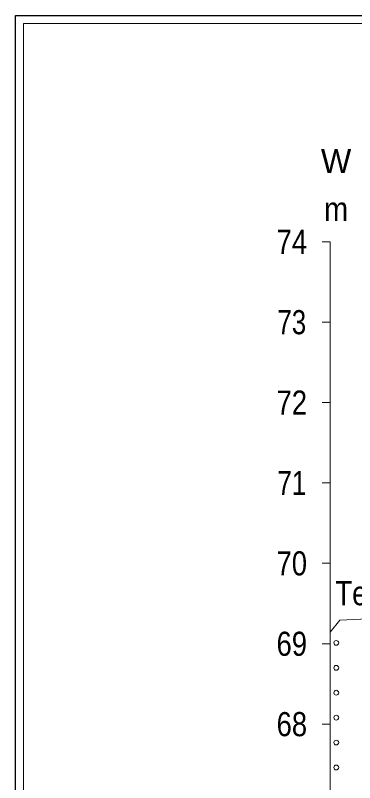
# Model space of a CAD drawing. Extents: x 640121 to 640955, y 6441885 to 6442246.
# Drawn here: x 640121.3 to 640163.5, y 6442150.7 to 6442246.2 of the extents above; entities that cross this region are included whole.
import ezdxf
from ezdxf.enums import TextEntityAlignment as Align

# ---------------------------------------------------------------- set-up
doc = ezdxf.new("R2010")
doc.units = 0
doc.header["$LTSCALE"] = 1.2
for name, color, linetype, lineweight in [('30', 7, 'Continuous', 13), ('31', 7, 'Continuous', 13), ('43', 7, 'Continuous', 13), ('50', 7, 'Continuous', 13)]:
    doc.layers.add(name, color=color, linetype=linetype, lineweight=lineweight)

msp = doc.modelspace()

# ---------------------------------------------------------------- linework, layer by layer
at = {"layer": '30'}
for p, q in [((640159.5, 6442218), (640160.5, 6442218)), ((640160.5, 6442063), (640160.5, 6442218)), ((640159.5, 6442208), (640160.5, 6442208)), ((640159.5, 6442198), (640160.5, 6442198)), ((640159.5, 6442188), (640160.5, 6442188)), ((640159.5, 6442178), (640160.5, 6442178)), ((640159.5, 6442168), (640160.5, 6442168)), ((640159.5, 6442158), (640160.5, 6442158))]:
    msp.add_line(p, q, dxfattribs=at)
at = {"layer": '31'}
msp.add_lwpolyline([(640160.5, 6442169.43), (640161.69, 6442170.91), (640166.93, 6442171.16)], dxfattribs=at)
at = {"layer": '43'}
for centre in [(640161.244, 6442168.096), (640161.244, 6442164.996), (640161.244, 6442161.896), (640161.244, 6442158.796), (640161.244, 6442155.696), (640161.244, 6442152.596)]:
    msp.add_circle(centre, 0.3, dxfattribs=at)
at = {"layer": '50', "lineweight": 25}
msp.add_lwpolyline([(640121.33, 6442246.16), (640955.23, 6442246.16), (640955.23, 6441889.4), (640121.33, 6441889.4)], close=True, dxfattribs=at)
at = {"layer": '50'}
msp.add_lwpolyline([(640122.33, 6442245.16), (640954.23, 6442245.16), (640954.23, 6441890.4), (640122.33, 6441890.4)], close=True, dxfattribs=at)

# ---------------------------------------------------------------- texts
at = {"layer": '30'}
msp.add_text('W', height=3, dxfattribs=at).set_placement((640161.225, 6442226.55), align=Align.CENTER)
for s, width, p in [('m', 0.9, (640161.23, 6442220.56)), ('74', 0.85, (640155.715, 6442216.49)), ('73', 0.8, (640155.715, 6442206.49)), ('72', 0.85, (640155.715, 6442196.49)), ('71', 0.8, (640155.72, 6442186.49)), ('70', 0.85, (640155.715, 6442176.49)), ('69', 0.85, (640155.715, 6442166.49)), ('68', 0.85, (640155.72, 6442156.49))]:
    msp.add_text(s, height=3, dxfattribs=dict(at, width=width)).set_placement(p, align=Align.CENTER)
at = {"layer": '31', "width": 0.85}
msp.add_text('Tee', height=3, dxfattribs=at).set_placement((640164.075, 6442172.78), align=Align.CENTER)

doc.saveas('drawing.dxf')
